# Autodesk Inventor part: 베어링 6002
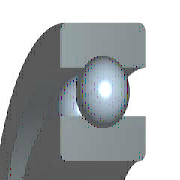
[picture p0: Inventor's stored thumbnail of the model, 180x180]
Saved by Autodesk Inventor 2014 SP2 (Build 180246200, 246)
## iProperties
IsCustomPart: 0
Created: 2012-02
Part Number: 베어링 6002
Material: 강철, 연강
Description: 깊은 그루브 볼 베어링
Document SubType Name: Modeling
Standard: KS B 2023
Designer: mduedu
Standards Organization: KS
Language: ko-KR
Size Designation: 6002 - 15 x 32 x 9
Categories: <MemberInstance><Categories><Category DisplayName="샤프트 부품" InternalName="7f7aeb1f-a693-4053-b835-cee3144e0d98" Mnemonic="SHFT"><Category DisplayName="베어링" Inter
Density: 1 g/cm^3
Appearance: 노란색
Author: mduedu
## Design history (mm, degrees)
sketch "스케치" dims "d0" = 4.42 (= -0.26 x WD + 0.26 x BD)
  geometry: L1 (2.29, 11.75)-(6.71, 11.75); L2 (4.5, 11.75)-(4.5, 9.54); L3 (4.5, 11.75)-(4.5, 13.96); L4 (2.858, 10.271)-(0, 10.271); L5 (0, 7.5)-(9, 7.5); L6 (2.858, 13.229)-(0, 13.229); L7 (0, 16)-(9, 16); L8 (9, 7.5)-(9, 10.271); L9 (6.142, 10.271)-(9, 10.271); L10 (6.142, 13.229)-(9, 13.229); L11 (9, 16)-(9, 13.229); L12 (-1.4, 0)-(8.4, 0) reference; L13 (0, -0.3)-(0, 5.3) reference
  constraints: 22 end point, 4 point on line, 2 collinear, 2 perpendicular, 2 symmetric about line, 1 midpoint, 1 parallel, 14 other
  dimensions: "d9" = 15 diameter of L5 L12 (= WD); "d11" = 32 diameter of L7 L12 (= BD); "d12" = 9 distance between parallel lines of L8 L13 (= KB); "d13" = 20.542 diameter of L9 L12 (= 0.326 x BD + 0.674 x WD)
revolve "본체" stored, may be unused: angle "d6" = 90 deg
revolve "볼" stored, may be unused: angle "d7" = 90 deg
pattern_circular "IDS_ARRAYBALL[SIMPL:T]" dims angle "d3" = 360 deg
body "Solid1"
fillet "모깎기1" dims "d1" = 0.3 (= KRS)
other parameters: "WD" = 15 [user parameter; used in 5 equation terms], "BD" = 32 [user parameter; used in 5 equation terms], "KB" = 9 [user parameter; used in 1 equation term], "KRS" = 0.3 [user parameter; used in 1 equation term], "d4" = 0, "d5" = 0, "d8" = 0, "d14" = 0, "d15" = 0, "BBA" = 0 [user parameter], "BC0" = 2850000 [user parameter], "BC" = 5590000 [user parameter], "BR" = 16 (= 0.5 x BD) [user parameter], "WR" = 7.5 (= 0.5 x WD) [user parameter]
